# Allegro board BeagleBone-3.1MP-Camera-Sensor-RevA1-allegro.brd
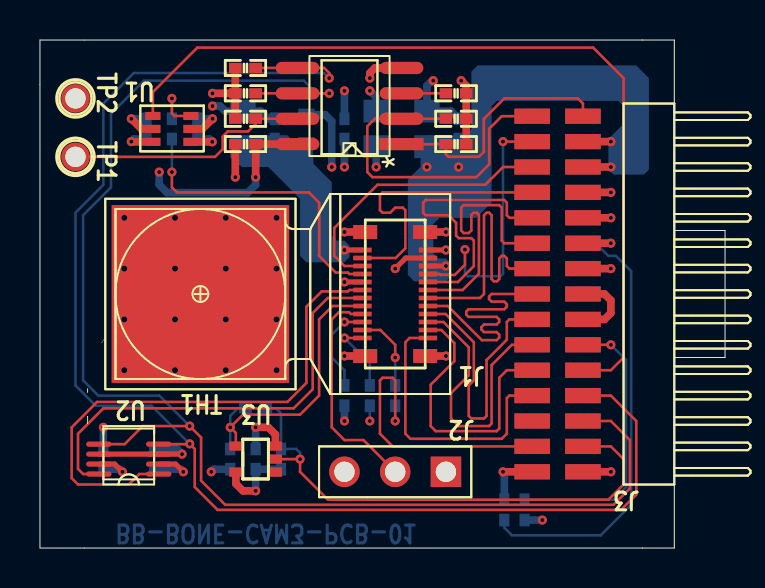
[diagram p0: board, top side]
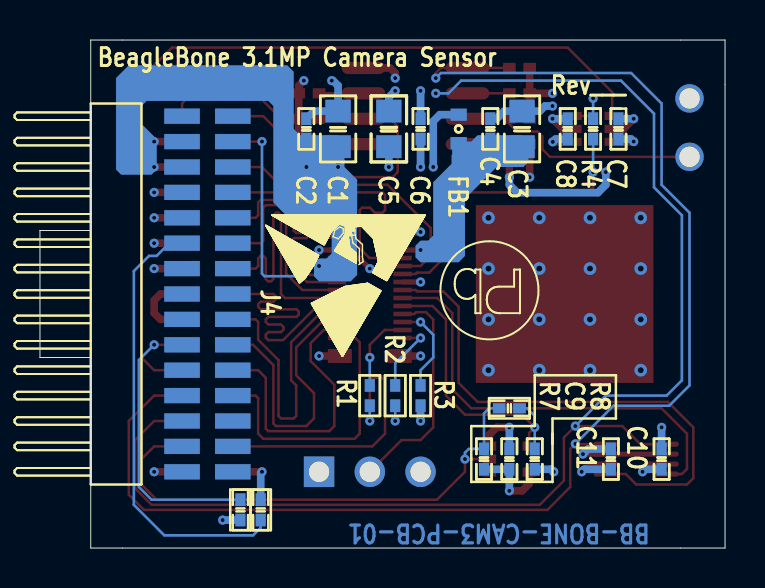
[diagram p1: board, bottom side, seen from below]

Outline 34.29 x 25.4 mm; copper layers: TOP, LYR2-GND, LYR3-PWR, BOTTOM. Coordinates in mm from the lower left corner of the outline.
Outline path: 0,25.4 0,0 31.75,0 31.75,9.53 34.29,9.53 34.29,15.88 31.75,15.88 31.75,25.4 0,25.4

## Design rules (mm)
net group CAM: nets CAM_D0 CAM_D1 CAM_D2 CAM_D3 CAM_D4 CAM_D5 CAM_D6 CAM_D7 CAM_D8 CAM_D9 CAM_HSYNC CAM_PCLK CAM_VSYNC

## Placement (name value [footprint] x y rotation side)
C1  10uF,10V  [805]  19.37 20.95 270 bottom
C2  0.1uF  [402]  20.95 20.95 270 bottom
C3  10uF,10V  [805]  10.16 20.95 270 bottom
C4  0.1uF  [402]  11.75 20.95 270 bottom
C5  10uF,10V  [805]  16.83 20.95 270 bottom
C6  0.1uF  [402]  15.24 20.95 270 bottom
C7  0.1uF  [402]  5.33 20.95 270 bottom
C8  0.1uF  [402]  7.87 20.95 270 bottom
C9  0.1uF  [402]  10.79 4.45 270 bottom
C10  0.1uF  [402]  3.17 4.45 90 bottom
C11  0.1uF  [402]  5.71 4.45 90 bottom
C37  0.1uF  [402]  10.29 20.19 0 top
FB1  MMZ1608R301A  [IND603-24X32]  13.34 20.95 270 bottom
J1  AXT524124  [HDR2X12SMD_P4MM_7P4X3P0]  17.78 12.7 90 top
J2  CON3  [SIP3]  20.32 3.81 270 top
J3  HEADER 15X2  [HDR2X15SMD_50LS_RA]  27.18 12.7 90 top
J4  HEADER 15X2  [HDR2X15SMD_50LS_RA]  27.18 12.7 270 bottom
NOREF  -  []  -268.79 -348.86 0 top
NOREF#2  -  []  -268.79 -348.86 0 top
R1  0  [0402]  17.78 7.62 270 bottom
R2  0  [0402]  16.51 7.62 270 bottom
R3  10K  [0402]  15.24 7.62 270 bottom
R4  33  [402]  6.6 20.95 270 bottom
R5  0, DNI  [402]  10.79 6.99 180 bottom
R7  10K  [402]  12.06 4.45 90 bottom
R8  10K  [402]  9.53 4.45 90 bottom
R9  10K  [402]  24.26 1.91 90 bottom
R10  10K  [402]  23.24 1.91 90 bottom
R49  5.6K,5%  [402]  10.29 22.73 0 top
R50  5.6K,5%  [402]  10.29 24 0 top
R51  4.75K  [402]  20.83 22.73 180 top
R52  4.75K  [402]  20.83 21.46 180 top
R53  4.75K  [402]  20.83 20.19 180 top
R54  10K  [402]  10.29 21.46 0 top
TH1  CAM_THERMAL  [THERM]  8.03 12.7 90 top
TP1  T POINT A  [TP]  1.78 19.56 0 top
TP2  T POINT A  [TP]  1.78 22.48 0 top
U1  SN74AVC1T45  [SC70-6]  6.6 20.95 90 top
U2  TXS0102DCU  [DCU8-10X50]  4.45 4.45 90 top
U3  SN74LVC1G07DCK  [DCK5]  10.79 4.45 90 top
U5  CAT24C256W  [SOIC_8]  15.49 22.1 90 top

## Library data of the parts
C1 C3 C5 = CAP_10uF_Y5V_10V_10%_0805
C2 C4 C6-C11 C37 = CAP,0.1uF
FB1 = IND,MMZ1608R301A: User Part Number: X; Tolerance: X
J1 = CONN RCPT 28
J2 = CON3
J3 J4 = HEADER 15X2
R1 R2 = ZeroOhmResistor1/16W0402
R3 R49 R50 R54 = RES_470_1/10W_5%_0402
R4 R5 = RES_33_0402
R7-R10 = RES_0: tolerance: 1%
R51-R53 = RES_4.7K_0402
TH1 = TEST POINT
TP1 TP2 = T POINT A_0
U1 = SN74AVC1T45
U2 = TXS0102DCU
U3 = SN74LVC1G06DCK_0: Tolerance: TOL; User Part Number: PART#
U5 = CAT24C256W

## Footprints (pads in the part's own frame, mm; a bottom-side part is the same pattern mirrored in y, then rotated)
402
  rect 0.635x0.508 smd: 1(-0.508,0) 2(0.508,0)
0402
  rect 0.635x0.508 smd: 1(-0.508,0) 2(0.508,0)
805
  rect 1.143x1.27 smd: 1(-0.889,0) 2(0.889,0)
DCK5
  rect 0.46x0.66 smd: 1(-0.65,-0.991) 2(0,-0.991) 3(0.65,-0.991) 4(0.65,0.991) 5(-0.65,0.991)
DCU8-10X50
  oval 0.254x1.27 smd: 1(-0.747,-1.499) 2(-0.249,-1.499) 3(0.249,-1.499) 4(0.747,-1.499) 5(0.747,1.499) 6(0.249,1.499) 7(-0.249,1.499) 8(-0.747,1.499)
HDR2X12SMD_P4MM_7P4X3P0
  rect 0.23x0.92 smd: 1(-2.2,-1.64) 2(-1.8,-1.64) 3(-1.4,-1.64) 4(-1,-1.64) 5(-0.6,-1.64) 6(-0.2,-1.64) 7(0.2,-1.64) 8(0.6,-1.64) 9(1,-1.64) 10(1.4,-1.64) 11(1.8,-1.64) 12(2.2,-1.64) 13(2.2,1.64) 14(1.8,1.64) 15(1.4,1.64) 16(1,1.64) 17(0.6,1.64) 18(0.2,1.64) 19(-0.2,1.64) 20(-0.6,1.64) 21(-1,1.64) 22(-1.4,1.64) 23(-1.8,1.64) 24(-2.2,1.64)
  rect 0.7x1.2 smd: 25(-3.1,-1.5) 26(3.1,-1.5) 27(3.1,1.5) 28(-3.1,1.5)
HDR2X15SMD_50LS_RA
  rect 0.762x1.778 smd: 1(-8.89,0) 2(-8.89,2.54) 3(-7.62,0) 4(-7.62,2.54) 5(-6.35,0) 6(-6.35,2.54) 7(-5.08,0) 8(-5.08,2.54) 9(-3.81,0) 10(-3.81,2.54) 11(-2.54,0) 12(-2.54,2.54) 13(-1.27,0) 14(-1.27,2.54) 15(0,0) 16(0,2.54) 17(1.27,0) 18(1.27,2.54) 19(2.54,0) 20(2.54,2.54) 21(3.81,0) 22(3.81,2.54) 23(5.08,0) 24(5.08,2.54) 25(6.35,0) 26(6.35,2.54) 27(7.62,0) 28(7.62,2.54) 29(8.89,0) 30(8.89,2.54)
IND603-24X32
  rect 0.61x0.813 smd: 1(-0.711,0) 2(0.711,0)
SC70-6
  rect 0.406x0.762 smd: 1(-0.648,-0.953) 2(0,-0.953) 3(0.648,-0.953) 4(0.648,0.953) 5(0,0.953) 6(-0.648,0.953)
SIP3
  rect 1.524x1.524 hole 1.016: 1(0,0)
  round 1.524 hole 1.016: 2(0,-2.54) 3(0,-5.08)
SOIC_8
  rect 0.61x2.184 smd: 1(-1.905,-2.603)
  oval 0.61x2.184 smd: 2(-0.635,-2.603) 3(0.635,-2.603) 4(1.905,-2.603) 5(1.905,2.603) 6(0.635,2.603) 7(-0.635,2.603) 8(-1.905,2.603)
THERM
  rect 8.89x8.89 smd: 1(0,0)
TP
  round 1.422 hole 1.016: 1(0,0)

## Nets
AVDD_2V8: C3.2 C4.2 FB1.2 J1.13
DGND: C1.1 C2.1 C3.1 C4.1 C5.1 C6.1 C7.1 C8.1 C9.1 C10.2 C11.1 C37.1 J1.12 J1.17 J1.25 J1.26 J1.27 J1.28 J2.3 J3.1 J3.2 R3.2 R10.2(P2) TH1.1 TP2.1(TP) U1.2(GND) U1.5(DIR) U2.2(GND) U3.3(GND) U5.4(VSS)
VDD_1V8: C1.2 C2.2 J1.10 J3.25 J3.27
VDD_2V8: C5.2 C6.2 C8.2 C10.1 FB1.1 J1.11 J2.1 J3.21 J3.23 R8.1(P1) U1.1(VCCA) U2.7(VCCB)
VDD_3V3: C7.2 C9.2 C11.2 C37.2 J3.17 J3.19 R7.1(P1) R9.1(P1) R49.1 R50.1 R51.1 R52.1 R53.1 R54.1 U1.6(VCCB) U2.3(VCCA) U2.6(OE) U3.5(VCC) U5.8(VCC)
CAM_D0: J3.4 R1.2(P2)
CAM_D1: J3.6
CAM_D2: J1.1 J3.8
CAM_D3: J1.2 J3.10
CAM_D4: J1.3 J3.12
CAM_D5: J1.4 J3.14
CAM_D6: J1.5 J3.16
CAM_D7: J1.6 J3.18
CAM_D8: J1.7 J3.20
CAM_D9: J1.8 J3.22
CAM_HSYNC: J1.15 J3.26
CAM_MCLK: J3.9 U1.4(B)
CAM_PCLK: J1.9 J3.28
CAM_RESET: J1.20 R5.2 R8.2(P2) U3.4(Y)
CAM_RST: J3.3 R5.1 R7.2(P2) U3.2(A)
CAM_SCL: J1.19 U2.8(B1)
CAM_SDA: J1.18 U2.1(B2)
CAM_STANDBY: J1.21 J2.2
CAM_VSYNC: J1.14 J3.24
CAMMCLK: J1.16 R4.2
FLASH: J1.24 R2.1(P1)
GPI/0: J1.23 R1.1(P1)
I2C2_SCL: J3.5 R49.2 U2.5(A1) U5.6(SCL)
I2C2_SDA: J3.7 R50.2 U2.4(A2) U5.5(SDA)
SAADDR: J1.22 R3.1
SW1_A0: J3.29 R53.2 U5.1(A0)
SW1_A1: J3.30 R52.2 U5.2(A1)
SW1_A3: R51.2 U5.3(A2)
SYS_5V: J3.13 J3.15
N17068201: R4.1 U1.3(A)
N17082554: J3.11 R9.2(P2)
N17092081: J4.11 R10.1(P1)
N17093440: R54.2 TP1.1(TP) U5.7(WP)

Pads without a net: J4 1 2 3 4 5 6 7 8 9 10 12 13 14 15 16 17 18 19 20 21 22 23 24 25 26 27 28 29 30; R2 2; U3 1

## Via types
v1: diameter 0.457, hole 0.203, TOP to BOTTOM, 61 vias
v2: diameter 0.635, hole 0.305, TOP to BOTTOM, 16 vias

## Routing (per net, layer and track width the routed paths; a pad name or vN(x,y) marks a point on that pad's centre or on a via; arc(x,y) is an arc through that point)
AVDD_2V8: length 0.9
  TOP w0.254: J1.13 v1(15.24,14.9)
DGND: length 43.3
  TOP w0.254: v1(7.18,3.81) 6.79,4.2 U2.2 ; J1.17 v1(15.24,13.3) ; J1.12 v1(20.32,14.9)
  TOP w0.381: J1.28 v1(15.24,9.6) ; U1.5 5.08,20.95 v1(4.57,21.46) ; J3.1 v1(28.57,3.81) ; C37.1 v1(9.78,18.54) ; U3.3 11.79,5.68 11.43,6.03 v1(10.79,6.03) ; v1(8.64,21.46) 8.13,20.95 U1.2 ; J1.26 v1(20.32,15.8) ; U5.4 16.76,24 16.51,23.75 v1(16.51,23.5) ; J1.27 v1(15.24,15.8) ; J1.25 v1(20.32,9.6) ; J3.2 v1(23.18,3.81)
  LYR2-GND w0.889: 14.47,3.04 J2.3 ; J2.3 16.01,4.58 ; J2.3 14.47,4.58 ; J2.3 16.01,3.04 ; 1.04,21.75 TP2.1 ; TP2.1 2.51,23.21 ; TP2.1 2.51,21.75 ; TP2.1 1.04,23.21
  BOTTOM w0.381: v1(19.68,23.37) 19.62,23.37 19.37,23.11 C1.1 20.57,21.84 20.95,21.46 ; v1(7.18,3.81) 7.05,3.94 5.71,3.94 ; 23.24,2.41 23.24,3.75 v1(23.18,3.81) ; C5.1 16.83,22.54 v1(16.51,22.86) ; 15.24,21.46 v1(15.24,22.86) ; 11.75,21.46 11.43,21.46 11.05,21.84 C3.1 9.27,21.84 9.02,22.1 v1(8.64,22.1) ; R3.2 v1(15.24,6.35) ; 7.87,21.46 v1(8.64,21.46) ; C10.2 v1(3.17,6.03) ; C9.1 v1(10.79,6.03) ; 5.33,21.46 v1(4.57,21.46)
  vias: v2(4.22,16.51) v2(4.22,13.97) v2(4.22,11.43) v2(4.22,8.89) v2(6.76,16.51) v2(6.76,13.97) v2(6.76,11.43) v2(6.76,8.89) v2(9.3,16.51) v2(9.3,13.97) v2(9.3,11.43) v2(9.3,8.89) v2(11.84,16.51) v2(11.84,13.97) v2(11.84,11.43) v2(11.84,8.89)
VDD_1V8: length 6.1
  TOP w0.254: J1.10 v1(20.32,14.1)
  TOP w0.381: J3.25 v1(28.57,19.05) ; J3.27 v1(28.57,20.32)
  BOTTOM w0.381: C2.2 v1(20.95,19.05) ; C1.2 v1(19.37,19.05)
VDD_2V8: length 18.9
  TOP w0.254: v1(4.13,3.81) 3.74,4.2 U2.7 ; J1.11 18.31,14.5 v1(17.78,13.97)
  TOP w0.381: J3.21 v1(28.57,16.51) ; J3.23 v1(28.57,17.78) ; U1.1 v1(8.62,20.31)
  LYR3-PWR w0.889: 19.3,4.83 J2.1 21.34,4.83
  BOTTOM w0.381: C6.2 v1(15.24,19.05) ; C8.2 8.48,20.45 v1(8.62,20.31) ; 9.53,3.94 8.7,3.94 v1(8.57,3.81) ; 3.17,3.94 4,3.94 v1(4.13,3.81) ; C5.2 v1(16.83,19.05) ; v1(14.61,19.05) 14.61,21.34 14.27,21.67 FB1.1
VDD_3V3: length 32.2
  TOP w0.254: v1(7.11,4.69) U2.3 U2.6
  TOP w0.381: U3.5 9.8,3.21 10.16,2.86 v1(10.79,2.86) ; v1(21.08,23.37) 21.34,23.11 R51.1 R52.1 R53.1 ; U1.6 4.58,20.31 v1(4.57,20.32) ; v1(10.79,18.54) C37.2 U5.8 ; J3.19 v1(28.57,15.24) ; J3.17 v1(28.57,13.97) ; R49.1 R50.1 ; R49.1 v1(8.64,22.73) ; R49.1 R54.1
  BOTTOM w0.381: 12.06,3.94 10.79,3.94 v1(10.79,2.86) ; R9.1 v1(25.15,1.4) ; v1(10.79,18.54) 10.79,18.16 10.4,17.77 6.36,17.77 5.97,18.16 v1(5.97,18.8) ; v1(7.11,4.69) 6.85,4.95 C11.2 ; C7.2 4.7,20.45 v1(4.57,20.32)
CAM_D0: length 14.2
  TOP w0.127: J3.4 17.65,5.08 17.02,5.71 17.02,8.38 17.14,8.51 17.65,8.51 17.78,8.38 v1(17.78,6.35)
  BOTTOM w0.127: v1(17.78,6.35) R1.2
CAM_D2: length 14.2
  TOP w0.127: J1.1 18.5,10.5 18.29,10.29 18.29,5.71 18.54,5.46 23.11,5.46 23.37,5.71 23.37,7.49 23.5,7.62 J3.8
CAM_D3: length 14.2
  TOP w0.127: J1.2 20.09,10.9 20.74,10.25 20.74,9.35 19.56,8.17 19.56,6.1 19.81,5.84 22.86,5.84 22.99,5.97 22.99,8.51 23.37,8.89 J3.10
CAM_D4: length 14.1
  TOP w0.127: J1.3 20.2,11.3 21.46,10.03 21.46,8.64 20.57,7.75 20.57,6.48 20.95,6.1 22.48,6.1 22.61,6.22 22.61,9.14 23.62,10.16 J3.12
CAM_D5: length 14.1
  TOP w0.127: J1.4 20.3,11.7 21.72,10.29 21.72,8.38 21.46,8.13 21.46,6.6 21.59,6.48 22.23,6.48 22.35,6.6 22.35,9.17 22.35,9.4 23.37,10.41 23.37,11.3 23.5,11.43 J3.14
CAM_D6: length 14.2
  TOP w0.127: J3.16 22.61,12.7 22.48,12.57 22.48,12.45 22.61,12.32 23.24,12.32 23.37,12.19 23.37,12.06 23.24,11.94 21.45,11.94 21.34,11.83 21.34,11.67 21.45,11.56 22.86,11.56 22.99,11.43 22.99,11.3 22.86,11.18 22.23,11.18 22.1,11.05 22.1,10.92 22.23,10.79 22.86,10.79 22.99,10.67 22.99,10.52 22.86,10.39 22.12,10.39 20.41,12.1 J1.5
CAM_D7: length 14.2
  TOP w0.127: J1.6 22.03,12.5 22.23,12.7 22.23,16.64 22.35,16.76 22.48,16.76 22.61,16.64 22.61,13.45 22.72,13.34 22.88,13.34 22.99,13.45 22.99,14.48 23.11,14.61 23.24,14.61 23.37,14.48 23.37,14.1 23.5,13.97 J3.18
CAM_D8: length 14.2
  TOP w0.127: J1.7 21.15,12.9 21.97,13.72 21.97,16.65 21.86,16.76 21.7,16.76 21.59,16.65 21.59,15.88 21.46,15.75 21.21,15.75 21.08,15.88 21.08,17.02 21.21,17.14 22.99,17.14 23.11,17.02 23.11,15.37 23.24,15.24 J3.20
CAM_D9: length 14.1
  TOP w0.127: J3.22 23.5,16.51 23.37,16.64 23.37,17.27 23.24,17.4 19.3,17.4 19.18,17.27 19.18,16.76 19.3,16.64 20.45,16.64 20.83,16.26 20.83,15.62 20.95,15.49 21.59,15.49 21.72,15.37 21.72,14.1 20.92,13.3 J1.8
CAM_HSYNC: length 14.2
  TOP w0.127: J1.15 15.24,14.1 14.73,14.61 14.73,16 16.89,18.16 22.29,18.16 23.18,19.05 J3.26
CAM_MCLK: length 42.6
  TOP w0.127: U1.4 5.65,22.8 7.87,25.02 27.69,25.02 29.21,23.5 29.21,9.53 28.57,8.89 J3.9
CAM_PCLK: length 14.1
  TOP w0.127: v1(21.27,14.92) 21.27,14.16 20.76,13.65 20.05,13.65 20,13.7 J1.9 ; J3.28 v1(23.18,20.32)
  BOTTOM w0.127: v1(23.18,20.32) 23.18,13.72 23.05,13.59 21.4,13.59 21.27,13.72 v1(21.27,14.92)
CAM_RESET: length 15
  TOP w0.127: U3.4 9.8,5.75 v1(9.53,6.03) 10.16,6.67 13.02,6.67 13.97,7.62 13.97,11.43 14.64,12.1 J1.20
  BOTTOM w0.127: R8.2 v1(9.53,6.03) 9.53,6.6 9.91,6.99 10.29,6.99
CAM_RST: length 26.5
  TOP w0.127: J3.3 28.57,5.08 29.21,4.45 29.21,3.17 28.45,2.41 14.41,2.41 13.02,3.81 v1(13.02,4.45) U3.2
  BOTTOM w0.127: R5.1 11.81,6.99 12.06,6.73 R7.2 12.83,4.95 13.02,4.76 v1(13.02,4.45)
CAM_SCL: length 22.2
  TOP w0.127: U2.8 2.16,3.7 1.91,3.95 1.91,5.71 3.17,6.99 12.7,6.99 13.65,7.94 13.65,11.75 14.41,12.5 J1.19
CAM_SDA: length 26.9
  TOP w0.127: J1.18 15.48,12.9 15.41,12.83 14.1,12.83 13.34,12.06 13.34,8.26 12.38,7.3 2.86,7.3 1.59,6.03 1.59,3.49 1.91,3.17 4.45,3.17 4.97,3.7 U2.1
CAM_STANDBY: length 11.2
  TOP w0.127: J1.21 15.56,11.7 15.47,11.79 14.96,11.79 14.61,11.43 14.61,6.03 15.24,5.4 16.19,5.4 J2.2
CAM_VSYNC: length 14.2
  TOP w0.127: J1.14 17.8,14.5 18.29,14.99 18.29,16.89 18.16,17.02 17.78,17.02 17.53,16.76 17.14,16.76 17.02,16.89 17.02,17.65 17.14,17.78 J3.24
CAMMCLK: length 15.3
  TOP w0.127: v1(6.6,18.8) 6.6,18.03 6.86,17.78 13.46,17.78 13.97,17.27 13.97,14.61 14.81,13.77 15.41,13.77 15.48,13.7 J1.16
  BOTTOM w0.127: v1(6.6,18.8) R4.2
FLASH: length 3.8
  TOP w0.127: J1.24 v1(15.24,10.5)
  BOTTOM w0.127: v1(15.24,10.5) 16.51,9.23 R2.1
GPI/0: length 4
  TOP w0.127: v1(17.78,9.53) 17.78,10.16 17.04,10.9 J1.23
  BOTTOM w0.127: R1.1 v1(17.78,9.53)
I2C2_SCL: length 71.1
  TOP w0.127: v1(14.48,22.73) U5.6 R49.2 ; J3.5 28.57,6.35 29.53,5.4 29.53,2.98 28.7,2.16 9.27,2.16 8.06,3.37 8.06,5.52 v1(7.49,6.1) 5.14,6.1 4.24,5.19 U2.5
  BOTTOM w0.127: v1(7.49,6.1) 5.97,7.62 2.92,7.62 2.16,8.38 2.16,16.64 3.56,18.03 3.56,21.72 5.21,23.37 13.21,23.37 13.84,22.73 v1(14.48,22.73)
I2C2_SDA: length 71.3
  TOP w0.127: J3.7 28.57,7.62 29.84,6.35 29.84,2.67 29.08,1.91 8.89,1.91 7.75,3.05 7.75,4.95 v1(7.49,5.21) 7.48,5.19 U2.4 ; R50.2 U5.5 14.22,24 14.48,23.75 v1(14.48,23.5)
  BOTTOM w0.127: v1(14.48,23.5) 14.22,23.75 4.7,23.75 3.17,22.23 3.17,18.16 1.78,16.76 1.78,8.13 2.79,7.11 5.59,7.11 v1(7.49,5.21)
Net_44: length 0.8
  BOTTOM w0.127: 16.51,7.11 v1(16.51,6.35)
SAADDR: length 4.6
  TOP w0.127: J1.22 v1(15.24,11.3)
  BOTTOM w0.127: R3.1 15.24,8.89 14.61,9.53 14.61,10.66 v1(15.24,11.3)
SW1_A0: length 12.6
  TOP w0.127: U5.1 R53.2 20.32,19.68 20.45,19.56 21.97,19.56 22.23,19.81 22.23,21.46 23.24,22.48 26.92,22.48 27.18,22.23 J3.29
SW1_A1: length 17
  TOP w0.127: J3.30 23.11,21.59 22.48,20.95 22.48,19.18 21.84,18.54 16.64,18.54 16.38,18.8 16.38,21.08 16.76,21.46 R52.2
SW1_A3: length 2.2
  TOP w0.127: U5.3 R51.2
SYS_5V: length 3.7
  TOP w0.381: J3.13 28.26,11.43 28.57,11.75 28.57,12.38 28.26,12.7 J3.15
N17068201: length 2.8
  TOP w0.127: v1(6.6,22.48) 6.6,21.73 6.73,21.6 U1.3
  BOTTOM w0.127: v1(6.6,22.48) 6.6,21.46
N17082554: length 14.2
  TOP w0.127: J3.11 v1(28.57,10.16)
  BOTTOM w0.127: v1(28.57,10.16) 29.34,9.4 29.34,3.05 28.7,2.41 24.26,2.41
N17092081: length 22.2
  BOTTOM w0.127: R10.1 23.24,1.02 23.62,0.64 28.07,0.64 29.59,2.16 29.59,13.84 28.83,14.61 28.45,14.61 27.81,15.24 J4.11
N17093440: length 12.4
  TOP w0.127: 12.89,21.46 R54.2 10.79,21.21 10.41,20.83 9.4,20.83 9.14,20.57 9.14,19.94 8.76,19.56 TP1.1

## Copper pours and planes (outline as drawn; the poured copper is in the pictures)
AVDD_2V8 on BOTTOM (solid shape): 12.7,20.32 13.65,20.32 13.65,19.68 13.68,19.65 13.68,19.21 14.61,18.29 14.61,15.62 14.86,15.37 15.24,15.37 15.49,15.11 15.49,14.54 15.24,14.29 13.34,14.29 13.02,14.61 13.02,17.46 11.43,19.05 10.1,19.05 9.84,19.3 9.84,20.32 10.16,20.64 12.38,20.64
DGND on LYR2-GND: 31.11,24.77 31.11,0.64 0.64,0.64 0.64,24.77
VDD_1V8 on BOTTOM (solid shape): 30.48,23.5 30.48,18.92 30.23,18.67 28.7,18.67 28.45,18.92 28.45,20.45 29.21,21.21 29.21,22.1 28.96,22.35 22.86,22.35 22.61,22.1 22.61,17.27 21.84,16.51 20,16.51 19.68,16.19 19.68,14.73 19.94,14.48 20.32,14.48 20.57,14.22 20.57,13.59 20.32,13.34 18.73,13.34 18.41,13.65 18.41,18.41 19.05,19.05 19.05,20.32 19.37,20.64 21.27,20.64 21.59,20.95 21.59,23.81 21.91,24.13 29.84,24.13
VDD_2V8 on LYR3-PWR: 31.11,20.95 31.11,16.19 26.99,16.19 26.67,15.88 26.67,2.86 26.35,2.54 13.34,2.54 12.06,3.81 9.53,3.81 8.89,3.17 8.26,3.17 7.94,3.49 7.94,5.4 7.62,5.71 5.71,5.71 5.4,5.4 5.4,2.54 5.08,2.22 2.86,2.22 2.54,2.54 2.54,15.62 5.02,18.1 7.3,18.1 7.62,18.41 7.62,20.95
VDD_3V3 on LYR3-PWR: 7.3,21.34 7.3,18.73 6.99,18.41 4.64,18.41 2.22,16 2.22,2.22 2.54,1.91 5.4,1.91 5.71,2.22 5.71,5.08 6.03,5.4 7.3,5.4 7.62,5.08 7.62,4.15 7.56,4.06 7.45,4.08 6.79,3.81 7.45,3.54 7.56,3.56 7.62,3.47 7.62,3.17 7.94,2.86 9.21,2.86 9.84,3.49 11.75,3.49 12.19,3.05 12.19,2.92 12.95,2.16 26.8,2.16 27.05,2.41 27.05,15.62 27.3,15.88 31.11,15.88 31.11,0.64 0.64,0.64 0.64,24.77 31.11,24.77 31.11,21.34

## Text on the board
BOTTOM: BB-BONE-CAM3-PCB-01 | LAYER 4 | SOLDER
Board Geometry/Soldermask Bottom: SMS
Ref Des/Silkscreen Bottom: Rev___ | BeagleBone 3.1MP Camera Sensor | C10 | C7 | R8 | R4 | C11 | C9 | C8 | R7 | C3 | C4 | FB1 | R3 | C6 | R2 | C5 | R1 | C1 | C2 | J4 | BSLK
User.Comments: Camera Cape
TOP: LAYER 1 | COMPONENT
Board Geometry/Soldermask Top: SMC
Ref Des/Silkscreen Top: U2 | U1 | TH1 | U3 | J2 | J1 | J3 | TSLK
LYR2-GND: LAYER 2 | GROUND
LYR3-PWR: LAYER 3 | POWER
DISPLAY_TOP: SPC
USER_PART_NUM_TOP: TSLKC
USER_PART_NUM_BOTTOM: BSLKC
DISPLAY_BOTTOM: SPS
DEVICE_TYPE_BOTTOM: DATE | DESIGN ENGR | PROJECT ENGR | ENGR MGR | NEXT ASSEMBLY | APPROVED | CHECKED | DRAFTING | ENGR | NONE | 1 OF 1 | 10.  LAYER 1 AND 4 SHALL BE IMPEDENCE CONTROLLED, FOR 5 MIL LINES TO BE,50 OHMS. | 1   TOTAL BOARD THICKNESS SHALL BE .062 +/- 10% INCHES. | 5.  APPLY LPI SILKSCREEN OR EQUIVALENT PER THE ARTWORK COLOR:BLACK. | 4.  SOLDERMASK ON BOTH SIDES OF THE BOARD SHALL BE S.M.O.B.C., LPI, COLOR WHITE. | 3.  MINIMUM TRACE AND SPACE SHALL BE .005 OF AN INCH. | 2.  COPPER PLATED SURFACE CONDUCTORS SHALL BE THE EQUIVALENT OF 1 OZ. COPPER | 8.  FINISHED BOARD SHALL BE FREE OF BURRS ON EDGES. | 7.  DRC'S MUST BE RAN ON THE GERBERS BEFORE BUILDING BOARDS UNLESS PRIOR | 6.  PLATED THRU HOLE SIZE TOLERANCES SHALL BE +/- .003 INCH. | 9.  SURFACE FINISH SHALL BE IMMERSION SILVER. | AFTER PLATING.  PLANE LAYERS SHALL BE 1 OZ. COPPER.  AVERAGE COPPER ON | THE WALL OF THE PLATED HOLE SHALL BE PER IPC CLASS 2. | ALL MATERIAL SHALL BE NEMA GRADE FR-4 OR EQUIVALENT. (Tg>=170 DEG. C) | APPROVAL IS GIVEN IN WRITING. | UNPLATED THRU HOLE SIZE TOLERANCES SHALL BE +/- .002 INCH. | LAYER 1 | LAYER 2 | NOTES: UNLESS OTHERWISE SPECIFIED
User.9: DATE | DESIGN ENGR | PROJECT ENGR | ENGR MGR | NEXT ASSEMBLY | APPROVED | CHECKED | DRAFTING | ENGR | 1 OF 1 | TOP SIDE | BOTTOM SIDE
User.10: NONE
User.12: 1. All board outlines shall be .020 in width. | 2. All other lines shall be .012 in width. | 3. Note and misc. text shall be text block 10. | 4. View and description text shall be text block 16. | 5. Make sure that there is not any double dimensioning, | 6. Check all notes to make sure that they apply and are correct. | 7. Make sure that layer stack-up is correct. | label (REF) dim when needed.
User.16: FIGURE | SIZE | 8.0 | 12.0 | 40.0 | ALL UNITS ARE IN MILS | DRILL CHART: TOP to BOTTOM | TOLERANCE | +3.0/-3.0 | PLATED | QTY | 61 | 16 | 5
